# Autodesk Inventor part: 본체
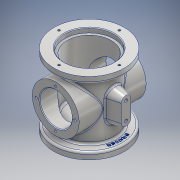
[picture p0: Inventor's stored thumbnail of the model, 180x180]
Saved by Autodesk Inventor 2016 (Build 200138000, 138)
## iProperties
Created: 2018-02
Part Number: 본체
Material: 알루미늄 6061
Document SubType Name: Modeling
Designer: 605-15
Density: 2.7 g/cm^3
Appearance: 알루미늄 - 평지
Mass: 831.863 g
Surface Area: 810.089 cm^2
Volume: 308.097 cm^3
Author: 605-15
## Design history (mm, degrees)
sketch "스케치2"
  geometry: L1 (-50, 0)-(50, 0); L2 (50, 0)-(50, 35); L3 (50, 35)-(-50, 35); L4 (-50, 35)-(-50, 0); 2 further points
  constraints: 8 end point, 2 parallel, 1 coincident, 1 horizontal, 1 midpoint, 1 perpendicular
  dimensions: "d4" = 100 distance of L3.end L2.end; "d5" = 70 diameter of L3 L1
revolve "회전2" sketch "스케치2" stored, may be unused: angle "d6" = 90 deg
sketch "스케치3"
  geometry: L1 (-38, 44)-(38, 44); L2 (38, 44)-(38, -44); L3 (38, -44)-(-38, -44); L4 (-38, -44)-(-38, 44); L5 (-52.5, -44)-(52.5, -44); L6 (52.5, -44)-(52.5, -54); L7 (52.5, -54)-(-52.5, -54); L8 (-52.5, -54)-(-52.5, -44); L9 (-52.5, 44)-(52.5, 44); L10 (52.5, 44)-(52.5, 54); L11 (52.5, 54)-(-52.5, 54); L12 (-52.5, 54)-(-52.5, 44); L13 (0, 54)-(0, -54); L14 (-34, -54)-(34, -54); L15 (-33, 54)-(33, 54); L16 (5, -38)-(-5, -38); L17 (34, -54)-(52.5, -54); L18 (52.5, -54)-(52.5, -44); L19 (52.5, -44)-(38, -44); L20 (38, -44)-(38, 44); L21 (38, 44)-(52.5, 44); L22 (52.5, 44)-(52.5, 54); L23 (52.5, 54)-(33, 54); 6 further points
  constraints: 46 end point, 8 midpoint, 6 parallel, 5 collinear, 5 horizontal, 5 perpendicular, 3 point on line, 1 horizontal alignment, 1 vertical alignment
  dimensions: "d7" = 76 distance of L2.end L3.end; "d8" = 105 distance of L6.end L7.end; "d9" = 10 distance of L5.end L6.end; "d10" = 105 distance of L11.end L10.end; "d11" = 10 distance of L10.end L9.end; "d12" = 54 distance from line of point (38, 0) L7; "d17" = 10 distance of L16.start L16.end
revolve "회전3" sketch "스케치3" stored, may be unused: angle "d18" = 90 deg
hole "구멍1" diameter "d21" = 66; stored, may be unused: countersink angle "d25" = 90 deg, drill point angle "d27" = 0 deg; dims "d22" = 6, "d23" = 4, "d24" = 2, "d26" = 86, "d113" = 10, "d114" = 10
hole "구멍2" diameter "d30" = 68; stored, may be unused: countersink angle "d34" = 90 deg, drill point angle "d36" = 0 deg; dims "d28" = 10, "d29" = 10, "d31" = 6, "d32" = 4, "d33" = 2, "d35" = 16
hole "구멍3" diameter "d39" = 10; stored, may be unused: countersink angle "d43" = 90 deg, drill point angle "d45" = 0 deg; dims "d37" = 10, "d38" = 10, "d40" = 6, "d41" = 4, "d42" = 2, "d44" = 16
hole "구멍4" diameter "d48" = 74; stored, may be unused: countersink angle "d52" = 90 deg, drill point angle "d54" = 0 deg; dims "d46" = 10, "d47" = 10, "d49" = 6, "d50" = 4, "d51" = 2, "d53" = 7
hole "구멍5" diameter "d57" = 48; stored, may be unused: countersink angle "d61" = 90 deg, drill point angle "d63" = 0 deg; dims "d55" = 10, "d56" = 10, "d58" = 6, "d59" = 4, "d60" = 2, "d62" = 7
sketch "스케치4" dims "d64" = 58
  geometry: 3 further points
  constraints: 2 vertical alignment, 1 coincident, 2 other
hole "구멍6" sketch "스케치4" at (0, -29) diameter "d65" = 3.459; stored, may be unused: countersink angle "d69" = 90 deg, drill point angle "d71" = 118 deg; dims "d66" = 4, "d67" = 4, "d68" = 2, "d70" = 6
sketch "스케치5" dims "d75" = 90
  geometry: 3 further points
  constraints: 2 vertical alignment, 1 coincident, 2 other
hole "구멍7" sketch "스케치5" at (0, 45) diameter "d76" = 3.242; stored, may be unused: countersink angle "d80" = 90 deg, drill point angle "d82" = 118 deg; dims "d77" = 4, "d78" = 4, "d79" = 2, "d81" = 6
node "작업 평면2"
sketch "스케치6"
  geometry: L1 (0, 20)-(0, -20); L2 (7, 13)-(7, -13); L3 (-7, 13)-(-7, -13); A1 r 7 centre (0, -13) between (0, -20) and (7, -13); A2 r 7 centre (0, 13) between (0, 20) and (7, 13); 2 further points
  constraints: 6 end point, 6 point on circle, 4 tangent, 2 centre point, 2 point on line, 1 coincident, 1 midpoint, 1 vertical
  dimensions: "d88" = 7 radius of A1; "d89" = 7 radius of A2; "d90" = 40 distance of L1.start L1.end
extrude "돌출1" join sketch "스케치6" stored distance "d91" = 10; taper "d92" = 15 deg
sketch "스케치7"
  geometry: L1 (13, 7)-(-13, 7) reference; L2 (-13, -7)-(13, -7) reference; A1 r 7 centre (13, 0) between (13, -7) and (13, 7) reference; A2 r 7 centre (-13, 0) between (-13, 7) and (-13, -7) reference; 3 further points
  constraints: 2 coincident
hole "구멍8" sketch "스케치7" at (-13, 0), (13, 0) diameter "d93" = 4.459; stored, may be unused: countersink angle "d97" = 90 deg, drill point angle "d99" = 118 deg; dims "d94" = 6, "d95" = 4, "d96" = 2, "d98" = 8
fillet "모깎기1" dims "d100" = 3
chamfer "모따기1" distance "d101" = 1; stored, may be unused: second distance "d102" = 2, angle "d103" = 45 deg
node "작업 평면3"
sketch "스케치8"
  geometry: C1 r 43 at (0, 0); 1 further point
  constraints: 1 centre point, 1 coincident, 1 other
  dimensions: "d105" = 86 diameter of C1
feature "엠보싱2" sketch "스케치8" dims "d4" = 100, "d5" = 70, "d7" = 76, "d8" = 105, "d9" = 10, "d10" = 105, "d11" = 10, "d12" = 54, "d109" = 0.5, "d110" = 0
node "솔리드2"
pattern_circular "원형 패턴1" dims angle "d73" = 360 deg
mirror "대칭1"
pattern_circular "원형 패턴2" dims angle "d84" = 360 deg
node "투영된 루프1"
other parameters: "d86" = 55, "d104" = 5
